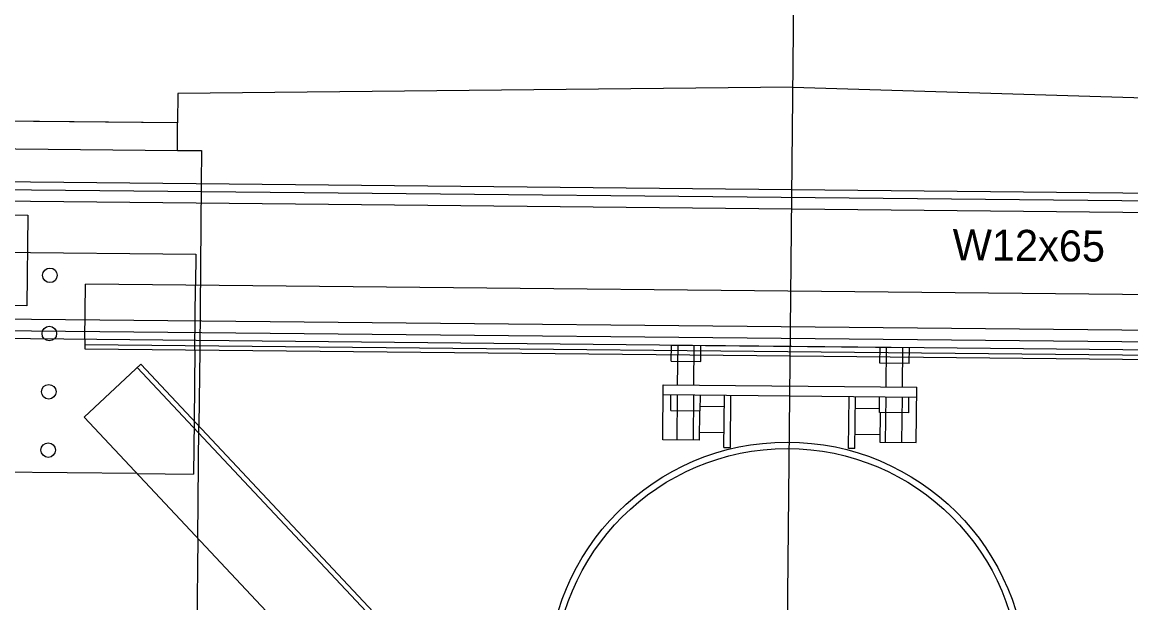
# Model space of a CAD drawing. Extents: x 632312 to 632425, y 378332 to 378413.
# Drawn here: x 632341.43 to 632348.57, y 378392.88 to 378396.62 of the extents above; entities that cross this region are included whole.
import ezdxf

# ---------------------------------------------------------------- set-up
doc = ezdxf.new("R2010")
doc.units = 0
for name, color, linetype in [('B_Boring', 7, 'Continuous'), ('B_Boring Annot', 7, 'Continuous'), ('R_Proposed Const Limits Cut', 7, 'Continuous'), ('R_Road Edge of Shoulder', 7, 'Continuous'), ('SHT_Dimensions', 7, 'Continuous')]:
    doc.layers.add(name, color=color, linetype=linetype)

msp = doc.modelspace()

# ---------------------------------------------------------------- linework, layer by layer
at = {"layer": 'B_Boring'}
for p, q in [((632342.4312, 378395.7908), (632342.5874, 378395.7892)), ((632342.5874, 378395.7892), (632342.5853, 378395.5746)), ((632351.9077, 378395.4819), (632340.8666, 378395.5917)), ((632351.9072, 378395.4315), (632340.8661, 378395.5413)), ((632340.802, 378395.3799), (632341.4686, 378395.3732)), ((632341.4686, 378395.3732), (632341.4628, 378394.7899)), ((632342.5495, 378395.1229), (632342.5495, 378395.1229)), ((632341.4628, 378394.7899), (632340.7962, 378394.7966)), ((632351.8982, 378394.5241), (632340.8571, 378394.6338)), ((632351.8977, 378394.4737), (632340.8566, 378394.5834)), ((632341.8357, 378394.5737), (632341.8351, 378394.5133)), ((632341.8351, 378394.5133), (632346.3766, 378394.4681)), ((632342.5747, 378394.5059), (632342.5698, 378394.0153)), ((632345.6103, 378394.434), (632345.6113, 378394.5362)), ((632347.143, 378394.5189), (632345.6112, 378394.5341)), ((632345.6509, 378394.281), (632345.6535, 378394.5357)), ((632345.7557, 378394.2799), (632345.7583, 378394.5347)), ((632345.7994, 378394.4321), (632345.8004, 378394.5343)), ((632346.9529, 378394.4207), (632346.9539, 378394.5228)), ((632346.9935, 378394.2676), (632346.9961, 378394.5224)), ((632347.0983, 378394.2666), (632347.1009, 378394.5213)), ((632347.142, 378394.4188), (632347.143, 378394.5209)), ((632345.6103, 378394.434), (632345.7994, 378394.4321)), ((632346.3766, 378394.4681), (632350.918, 378394.423)), ((632347.142, 378394.4188), (632346.9529, 378394.4207)), ((632345.5549, 378393.927), (632345.5584, 378394.2819)), ((632345.5584, 378394.2819), (632347.1908, 378394.2656)), ((632345.5578, 378394.2187), (632347.1902, 378394.2024)), ((632345.6071, 378394.116), (632345.6081, 378394.2182)), ((632345.6474, 378393.926), (632345.6503, 378394.2178)), ((632345.7522, 378393.925), (632345.7551, 378394.2167)), ((632345.7963, 378394.1142), (632345.7973, 378394.2163)), ((632345.9493, 378393.8789), (632345.9527, 378394.2147)), ((632345.9904, 378393.8785), (632345.9937, 378394.2143)), ((632346.7509, 378393.871), (632346.7542, 378394.2068)), ((632346.792, 378393.8706), (632346.7953, 378394.2064)), ((632346.9497, 378394.1027), (632346.9507, 378394.2048)), ((632346.99, 378393.9127), (632346.9929, 378394.2044)), ((632347.1873, 378393.9107), (632347.1908, 378394.2656)), ((632345.9519, 378394.1398), (632345.7965, 378394.1414)), ((632347.0948, 378393.9116), (632347.0977, 378394.2034)), ((632347.1389, 378394.1008), (632347.1399, 378394.2029)), ((632345.6071, 378394.116), (632345.7963, 378394.1142)), ((632345.7909, 378394.1142), (632345.789, 378393.9246)), ((632346.7946, 378394.1314), (632346.95, 378394.1299)), ((632347.1389, 378394.1008), (632346.9497, 378394.1027)), ((632346.9551, 378394.1026), (632346.9532, 378393.9131)), ((632345.789, 378393.9246), (632345.5549, 378393.927)), ((632345.9503, 378393.9718), (632345.7895, 378393.9734)), ((632346.7929, 378393.9634), (632346.9537, 378393.9619)), ((632345.9493, 378393.8789), (632345.9904, 378393.8785)), ((632346.792, 378393.8706), (632346.7509, 378393.871)), ((632346.9532, 378393.9131), (632347.1873, 378393.9107)), ((632342.1707, 378393.7099), (632341.1605, 378393.72)), ((632342.5626, 378393.2924), (632342.5209, 378389.0953))]:
    msp.add_line(p, q, dxfattribs=at)
msp.add_lwpolyline([(632342.4312, 378395.7908), (632342.4329, 378395.9678), (632339.0998, 378396.001), (632339.098, 378395.8239)], close=True, dxfattribs=at)
for points in [[(632342.5434, 378394.5063), (632342.5389, 378394.0483)], [(632344.3046, 378391.4363), (632341.8307, 378394.0721), (632342.1953, 378394.4143), (632344.3118, 378392.1593)]]:
    msp.add_lwpolyline(points, dxfattribs=at)
for centre, radius in [((632341.6106, 378394.9864), 0.0469), ((632341.6069, 378394.6114), 0.0469), ((632341.6032, 378394.2364), 0.0469), ((632341.5995, 378393.8614), 0.0469), ((632346.3557, 378392.3708), 1.5417), ((632346.3557, 378392.3708), 1.5)]:
    msp.add_circle(centre, radius, dxfattribs=at)
at = {"layer": 'B_Boring Annot'}
for p, q in [((632342.4348, 378396.1574), (632342.4329, 378395.9678)), ((632346.3937, 378396.1972), (632342.4348, 378396.1574)), ((632346.3937, 378396.1972), (632350.3511, 378396.0787)), ((632342.4329, 378395.9678), (632339.0998, 378396.001))]:
    msp.add_line(p, q, dxfattribs=at)
at = {"layer": 'R_Proposed Const Limits Cut'}
for p, q in [((632342.5853, 378395.5746), (632342.5747, 378394.5059)), ((632351.9065, 378395.3569), (632340.8654, 378395.4667)), ((632341.1746, 378395.1366), (632342.5495, 378395.1229)), ((632342.5495, 378395.1229), (632342.5476, 378394.9229)), ((632341.8357, 378394.5737), (632341.8393, 378394.9299)), ((632350.9221, 378394.8396), (632341.8393, 378394.9299)), ((632342.5434, 378394.5063), (632342.5476, 378394.9229)), ((632351.899, 378394.5986), (632340.8578, 378394.7084)), ((632350.9183, 378394.449), (632341.8354, 378394.5393)), ((632342.1725, 378394.3929), (632350.8037, 378385.1968)), ((632342.5389, 378394.0483), (632342.5355, 378393.7063)), ((632342.5626, 378393.2924), (632342.5698, 378394.0153)), ((632342.1707, 378393.7099), (632342.5355, 378393.7063))]:
    msp.add_line(p, q, dxfattribs=at)
at = {"layer": 'R_Road Edge of Shoulder'}
msp.add_line((632346.2256, 378379.2847), (632346.5561, 378412.5263), dxfattribs=at)

# ---------------------------------------------------------------- texts
at = {"layer": 'SHT_Dimensions'}
msp.add_text('W12x65', height=0.2, rotation=359.43036, dxfattribs=at).set_placement((632347.4202, 378395.0836))

doc.saveas('drawing.dxf')
